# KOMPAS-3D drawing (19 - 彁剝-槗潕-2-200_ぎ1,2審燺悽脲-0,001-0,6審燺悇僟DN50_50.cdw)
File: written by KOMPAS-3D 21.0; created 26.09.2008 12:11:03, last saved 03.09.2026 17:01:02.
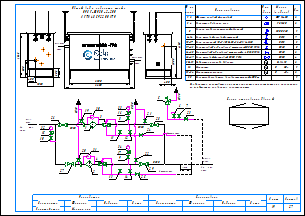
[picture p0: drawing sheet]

Sheets 1-2: A3, landscape

Document properties: Наименование: Макро:21; Автор: RaskoAdmin; Форматы листов документа: 2xA3; Полное имя файла: \\UR38nt01\Departments\КТО\КБ ПУРДГ\Заявки\Прайс-лист на типовые шкафы ГРПШ\ПРДГ_стандарт_20_03_2026\ПРДГ с РДГ(Н, В)\ПРДГ-ШУЭО-2-200_до1,2МПа_Рвых-0,001-0,6МПа_РДГ_DN50_50.cdw

Title block, sheet 1: Наименование: Пункт учета газа / ПУГ-Ш-400-Р / ЛГТИ.485922.001ТУ; designation: ЛГТИ.03.4411141; sheet number: 1; Количество листов документа: 2; organisation: ООО "ЭЛЬСТЕР Газэлектроника"; Форматы листов документа: A3; stored path: C:\Рабочие документы\Компас\ПУГ\Схема.cdw; Разработал: Устинов; Проверил: Кошкин; Утвердил: Кошкин
Title block, sheet 2: sheet number: 2; stored path: D:\Рабочие документы\Заявки\ПУРДГ\ПУРДГ-ШУЭО-2-100-Р 4411220.cdw; designation, second copy: ЛГТИ.03.4411141-

Views: Вид 1, Вид 2
Referenced files: wcvoit.frw
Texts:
  Normal
  Вход
  газа
  PDI
  Выход
  Р=     кПа
  DN50
  DN20
  Импульс DN20
  ≥5DN
  HYSWLongFangSong
  № на
  схеме
  Усл.
  обозн.
  Марка
  (модель)
  Кол.
  Фильтр газовый фланцевый
  ФГ 16-50
  Регулятор давления газа
  РДГ-50
  Клапан предохранительный сбросной
  КПС DN20
  Кран шаровой газовый латунный
  DN15
  Кран кнопочный VE-РАСКО-НЗ-1,6-G1/2-М20
  Кран шаровой "под приварку" штуцерный DN20 PN16
  Кран шаровой "под приварку" штуцерный п/п DN20 PN16
  Кран шаровой фланцевый DN50 PN16
  Индикатор перепада давления
  Delta 15
  Манометр
  Манометр-напоромер
  Электрообогреватель взрывозащищенный 400Вт
  0...     МПа
  0...     кПа
  Общий вид и габариты шкафа
  ПРДГ-ШУЭО-2-200
  Выход газа
  Вход газа
  Р=       МПа
  logo-rasko-ge.png
  Схема открывания дверей
  Предприятие изготовитель может заменять комплектующие на аналогичные,
  не ухудшающие заявленных характеристик.
  Должность
  Конструктор
  Фамилия
  Подпись
  Дата
  Согласовано
  Максимкин
  Лист
  Листов
  POLYLINE_STYLE_0.18_RGB_0_0_0
  POLYLINE_STYLE_0.50_RGB_0_0_0
  POLYLINE_STYLE_0.34_RGB_0_0_0
  PHANTOM_RGB_0_0_0_SC_1_THICK_0.18
  K5LT_THIN_RGB_0_0_0_THICK_0.18
  K5LT32769_RGB_0_0_0_THICK_0.18
  K5LT12_RGB_0_0_0_SC_1_THICK_0.18
  K5LT_DASHED_RGB_0_0_0_SC_1_THICK_0.18
  ACISOTGL_RGB_0_0_0_SC_0.8_THICK_0.25
  CONTINUOUS_RGB_0_127_31_THICK_0.3
  CONTINUOUS_RGB_0_0_255_THICK_0.35
  CONTINUOUS_RGB_255_0_0_THICK_0.35
  POLYLINE_STYLE_0.25_RGB_0_0_0
  CONTINUOUS_RGB_0_0_0_THICK_0.5
  POLYLINE_STYLE_0.35_RGB_0_0_255
  CONTINUOUS_RGB_0_0_0_THICK_0.4
  CONTINUOUS_RGB_0_0_0_THICK_0.35
  Без оформления
Dimensions and other numbers on the sheet: 1; 2; 3; 4; 5; 10; 27; 28; 29; 23; 8; 12; 19; 20; 21; 22; 25; 24; 30; 31; 15; 16; 26; 6; 7; 11; 14; 13; 33; 1, 2; 3, 4; 6-14; 9; 15-17; 19-23; 24-25; 26-29; 30-31; 32; 33-34; 35; 1000; 400; 1050; 500; 305; 2300; 4130; 1565; 2600; 17; 34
